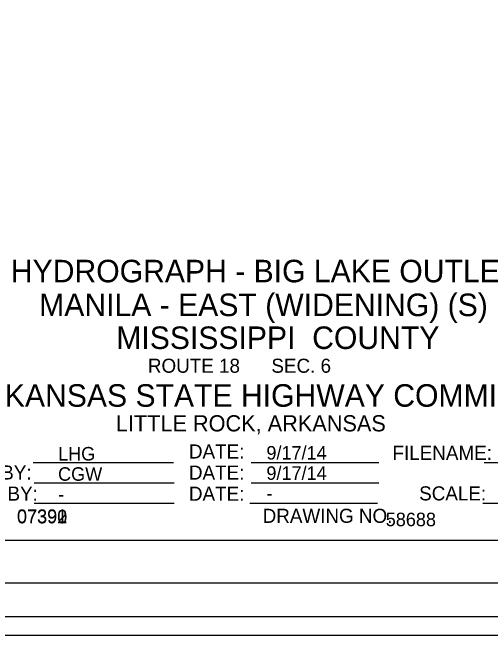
# Model space of a CAD drawing. Extents: x -1063117.9 to -1063075.9, y -253323.6 to -253301.6.
# Drawn here: x -1063089.92 to -1063085.67, y -253323.61 to -253318.07 of the extents above; entities that cross this region are included whole.
import ezdxf

# ---------------------------------------------------------------- set-up
doc = ezdxf.new("R2010")
doc.units = 0
for name, color, linetype in [('border', 7, 'Continuous'), ('Border 2660-Hwy18 - Level 62', 7, 'Continuous'), ('Border 2660-Hwy18 - Level 63', 7, 'Continuous'), ('Border 2660-Hwy18 - Text', 7, 'Continuous'), ('Border 2660-Hwy18 - Title Text', 7, 'Continuous'), ('Bridge No BLFR', 7, 'Continuous'), ('Bridge No BLO', 7, 'Continuous'), ('Bridge No Ditch 81', 7, 'Continuous'), ('Level 62 PDF', 7, 'Continuous'), ('Text', 7, 'Continuous'), ('Title Block Text', 7, 'Continuous'), ('Title Text', 7, 'Continuous')]:
    doc.layers.add(name, color=color, linetype=linetype)

msp = doc.modelspace()

# ---------------------------------------------------------------- linework, layer by layer
at = {"layer": 'border'}
for p, q in [((-1063089.7331, -253322.0701), (-1063088.4899, -253322.0701)), ((-1063087.7999, -253322.0712), (-1063086.666, -253322.0712)), ((-1063085.73, -253322.0712), (-1063084.3939, -253322.0712)), ((-1063089.7259, -253322.2501), (-1063088.4827, -253322.2501)), ((-1063087.7999, -253322.2512), (-1063086.666, -253322.2512)), ((-1063089.7259, -253322.4301), (-1063088.4827, -253322.4301)), ((-1063087.8107, -253322.4312), (-1063086.6768, -253322.4312)), ((-1063085.7424, -253322.4312), (-1063084.5768, -253322.4312)), ((-1063084.146, -253322.7613), (-1063116.1571, -253322.7613))]:
    msp.add_line(p, q, dxfattribs=at)
at = {"layer": 'Border 2660-Hwy18 - Level 62'}
msp.add_lwpolyline([(-1063117.7772, -253301.6304), (-1063083.6588, -253301.6304), (-1063083.6588, -253323.4399), (-1063117.7772, -253323.4399)], close=True, dxfattribs=at)
at = {"layer": 'Border 2660-Hwy18 - Level 63'}
msp.add_lwpolyline([(-1063117.8883, -253301.7733), (-1063083.8888, -253301.7733), (-1063083.8888, -253323.1428), (-1063117.8883, -253323.1428)], close=True, dxfattribs=at)
at = {"layer": 'Level 62 PDF'}
msp.add_lwpolyline([(-1063117.5272, -253301.797), (-1063083.4088, -253301.797), (-1063083.4088, -253323.6065), (-1063117.5272, -253323.6065)], close=True, dxfattribs=at)

# ---------------------------------------------------------------- texts
at = {"layer": 'Border 2660-Hwy18 - Text'}
for s, p in [('DATE:', (-1063088.3519, -253322.0346)), ('FILENAME:', (-1063086.545, -253322.0467)), ('CHECKED BY:', (-1063090.8815, -253322.2211)), ('DATE:', (-1063088.3519, -253322.2221)), ('DESIGNED BY:', (-1063090.8815, -253322.4086)), ('DATE:', (-1063088.3519, -253322.4096)), ('SCALE:', (-1063086.3084, -253322.4067)), ('DRAWING NO.', (-1063087.6976, -253322.606))]:
    msp.add_text(s, height=0.125, dxfattribs=at).set_placement(p)
at = {"layer": 'Border 2660-Hwy18 - Title Text'}
for s, height, p in [('MISSISSIPPI  COUNTY', 0.199999, (-1063088.9969, -253321.0622)), ('ROUTE 18      SEC. 6', 0.125, (-1063088.7161, -253321.2733)), ('ARKANSAS STATE HIGHWAY COMMISSION', 0.199999, (-1063090.3573, -253321.5749)), ('LITTLE ROCK, ARKANSAS', 0.144, (-1063089.0011, -253321.7941))]:
    msp.add_text(s, height=height, dxfattribs=at).set_placement(p)
at = {"layer": 'Bridge No BLFR'}
msp.add_text('07392', height=0.12, dxfattribs=at).set_placement((-1063089.8782, -253322.6106))
at = {"layer": 'Bridge No BLO'}
msp.add_text('07391', height=0.12, dxfattribs=at).set_placement((-1063089.8782, -253322.6061))
at = {"layer": 'Bridge No Ditch 81'}
msp.add_text('07390', height=0.12, dxfattribs=at).set_placement((-1063089.8782, -253322.6106))
at = {"layer": 'Text'}
for s, p in [('9/17/14', (-1063087.6644, -253322.0441)), ('LHG', (-1063089.5136, -253322.0523)), ('CGW', (-1063089.5136, -253322.2323)), ('9/17/14', (-1063087.6644, -253322.2241)), ('-', (-1063089.5136, -253322.4123)), ('-', (-1063087.6644, -253322.4041))]:
    msp.add_text(s, height=0.12, dxfattribs=at).set_placement(p)
at = {"layer": 'Title Block Text'}
msp.add_text('58688', height=0.12, dxfattribs=at).set_placement((-1063086.6054, -253322.6357))
at = {"layer": 'Title Text'}
for s, p in [('HYDROGRAPH - BIG LAKE OUTLET', (-1063089.9325, -253320.4702)), ('MANILA - EAST (WIDENING) (S)', (-1063089.681, -253320.7702))]:
    msp.add_text(s, height=0.199999, dxfattribs=at).set_placement(p)

doc.saveas('drawing.dxf')
